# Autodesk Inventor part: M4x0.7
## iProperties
IsCustomPart: 1
Created: 2009-02
Part Number: M4x0.7
Material: 강, 연강
Description: 6각머리 태핑 나사
Document SubType Name: Modeling
Standard: KS B 1003
Designer: SeoGD™[esajin.kr]
Standards Organization: KS
Language: ko-KR
Size Designation: M 4 x 16
Categories: <MemberInstance><Categories><Category DisplayName="조임쇠" InternalName="e4da775c-781d-43d5-af7c-5136215cf5a6" Mnemonic="FSTN"><Category DisplayName="볼트" InternalN
Density: 1 g/cm^3
Author: SeoGD™[esajin.kr]
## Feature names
1. Fillet2
